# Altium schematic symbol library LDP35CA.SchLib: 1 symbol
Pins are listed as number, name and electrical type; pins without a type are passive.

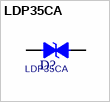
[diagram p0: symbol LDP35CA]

## LDP35CA
designator D?
footprint ST_R6B
pins: 1, 2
